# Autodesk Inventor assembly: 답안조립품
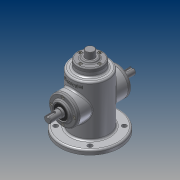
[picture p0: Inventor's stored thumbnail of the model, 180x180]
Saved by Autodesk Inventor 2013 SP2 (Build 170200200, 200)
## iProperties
Created: 2014-12
Part Number: 답안조립품
Document SubType Name: Assembly
Designer: CADB102
Author: CADB102
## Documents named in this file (12)
- C:\Users\CADB102\Desktop\441228V1015\답안조립품.iam
- C:\Users\CADB102\Desktop\441228V1015\1-본체.ipt
- C:\Users\CADB102\Desktop\441228V1015\2-편심축.ipt
- C:\Users\CADB102\Desktop\441228V1015\M3x0.5x8.ipt
- M3x0.5.ipt
- C:\Users\CADB102\Desktop\441228V1015\베어링 6002.ipt
- 베어링 6002.ipt
- C:\Users\CADB102\Desktop\441228V1015\상단커버.ipt
- C:\Users\CADB102\Desktop\441228V1015\슬라이드.ipt
- C:\Users\CADB102\Desktop\441228V1015\오일실.ipt
- 오일실.ipt
- C:\Users\CADB102\Desktop\441228V1015\커버.ipt
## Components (14 placed, 3 different names)
1. 1-본체:1
2. 2-편심축:1 — 구동
3. M3x0.5:3 — 각도:2
4. M3x0.5:2 — 각도:3
5. M3x0.5:4
6. M3x0.5:5
7. M3x0.5:6
8. M3x0.5:7
9. M3x0.5:8
10. M3x0.5:9
11. M3x0.5:1 — 각도:1
12. M3x0.5:10
13. M3x0.5:11
14. M3x0.5:12
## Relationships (4: Angle 4)
- 각도:1 [Angle]: M3x0.5:1
- 각도:2 [Angle]: M3x0.5:3
- 각도:3 [Angle]: M3x0.5:2
- 구동 [Angle]: 2-편심축:1
